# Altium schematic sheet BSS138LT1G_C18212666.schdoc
size 127 x 101 mm
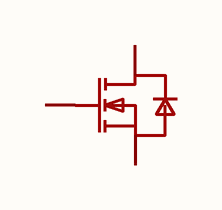
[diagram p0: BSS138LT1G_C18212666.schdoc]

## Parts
Q?  bss138lt1g_c18212666  [SOT-23-3_L2.9-W1.6-P1.90-LS2.8-BR]  (value not drawn)

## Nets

Not connected (* = marked no-connect by the designer): Q? 1(G) 2(S) 3(D)

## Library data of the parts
Q? = bss138lt1g_c18212666: 漏源电压(Vdss):50V;连续漏极电流(Id):360mA;导通电阻(RDS(on)):4.5Ω@2.5V,0.1A;耗散功率(Pd):350mW;阈值电压(Vgs(th)):1.5V@250uA;; Manufacturer: TECH PUBLIC(台舟); AddInBom: yes; ModelId: 89cb27a44ab2466697082bb9fd73a7d0; ModelName: SOT-23-3L_L2.9-W1.6-H1.1-LS2.8-P0.95; ModelTransform: 114.173,110.236,0,90,0,0,0,0,0; Drain to Source Voltage: 50V; Current - Continuous Drain(Id): 360mA; Pd - Power Dissipation: 350mW; Gate Charge(Qg): 4nC@10V; Input Capacitance(Ciss): 32pF; Reverse Transfer Capacitance (Crss@Vds): 3pF; Type: N沟道; Output Capacitance(Coss): 6pF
